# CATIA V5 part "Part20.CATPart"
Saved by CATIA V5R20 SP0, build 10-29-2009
Part number: JT10x2
Revision: ANY
Definition: UNKNOWN
Nomenclature: JT10x2
Source: Unknown
Bounding box of the stored display mesh (mm): x -6.824 to 6.824, y -1 to 1, z -7 to 7
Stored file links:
  C:\Users\Utente\Desktop\IO LAVORO\3D X SITO CF\CUMSA\3D files SA\SA 160416\Part20.CATPart
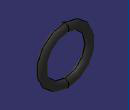
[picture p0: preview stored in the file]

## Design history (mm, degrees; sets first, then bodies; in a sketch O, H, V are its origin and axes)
Body1 "Revolución1" (main body)
  Solid1: solid without history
